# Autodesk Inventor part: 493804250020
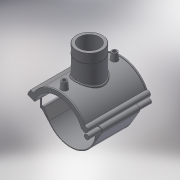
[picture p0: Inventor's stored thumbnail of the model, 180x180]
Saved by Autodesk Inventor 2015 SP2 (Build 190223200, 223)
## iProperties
Created: 2017-07
Part Number: 493804250020
Material: Generic
Description: PLASSON TRANSITION SADDLE 250-2"
Document SubType Name: Modeling
Designer: KIM
Density: 1 g/cm^3
Appearance: Default
Author: KIM
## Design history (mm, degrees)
derived "493804.ipt"
feature "Solid1::493804.ipt"
tag "TaggingFeature1"
body "Solid1"
other parameters: "d1" = 287.5, "d2" = 327.6, "d3" = 62.5, "d4" = 176, "d5" = 0, "d6" = 0.1, "d8" = 0, "d19" = 6, "d20" = 6, "d21" = 105.6, "d23" = 0, "d24" = 52.8, "d26" = 0, "d27" = 3, "d28" = 3, "d29" = 3, "d30" = 83.33333, "d31" = 6, "d32" = 0, "d33" = 0, "d34" = 0.6, "d40" = 149.5, "d41" = 79.3184, "d43" = 0, "d45" = 0, "d47" = 219.75, "d48" = 73.6528, "d50" = 0, "d70" = 15, "d72" = 0, "d73" = 6, "d75" = 5, "d76" = 0, "d77" = 12.5, "d78" = 155, "d79" = 15, "d80" = 70.4, "d82" = 5 deg, "d84" = 4, "d85" = 14, "d86" = 0, "d87" = 3, "d88" = 0, "d89" = 1, "d90" = 1, "d91" = 140.8, "d92" = 0, "d93" = 0.5, "d94" = 131.57895, "d96" = 293.25, "d97" = 3.52, "d98" = 0, "d102" = 1.69968, "d103" = 56.656, "d104" = 45.6, "d105" = 0, "d106" = 45.3248, "d108" = 0, "d109" = -25.33333, "d111" = 0.5, "d112" = 0.5, "d113" = 0, "d114" = 0.5, "d117" = 0.56656, "d120" = 140 deg, "d121" = 24.228, "d122" = 20 deg, "d123" = 575, "d124" = 172.5, "d126" = 0, "d143" = 257.5, "d145" = 28.84615, "d149" = 3.75, "d150" = 31.73077, "d153" = 176, "d154" = 0, "d156" = 143.75, "d157" = 160 deg, "d159" = 7.5, "d161" = 3.75, "d162" = 105.6, "d163" = 0, "d164" = 125, "d167" = 25, "d168" = 140.2439, "d170" = 3.75, "d172" = 0, "d173" = 1, "d175" = 125, "d176" = 20 deg, "d177" = 17.5, "d178" = 37.5, "d180" = 0, "d183" = 15, "d184" = 14, "d185" = 57.2, "d186" = 57.2, "d187" = 143.75, "d188" = 11.25, "d189" = 17.5, "d190" = 0, "d191" = 172.5, "d193" = 7.5, "d194" = 4.4, "d195" = 90 deg, "d197" = 0, "d199" = 0, "B_" = 252, "H_" = 76, "L_" = 176, "d_t" = 6, "G_" = 56.656, "d148" = 3.75, "d160" = 3.75, "d169" = 3.75, "d192" = 7.5
